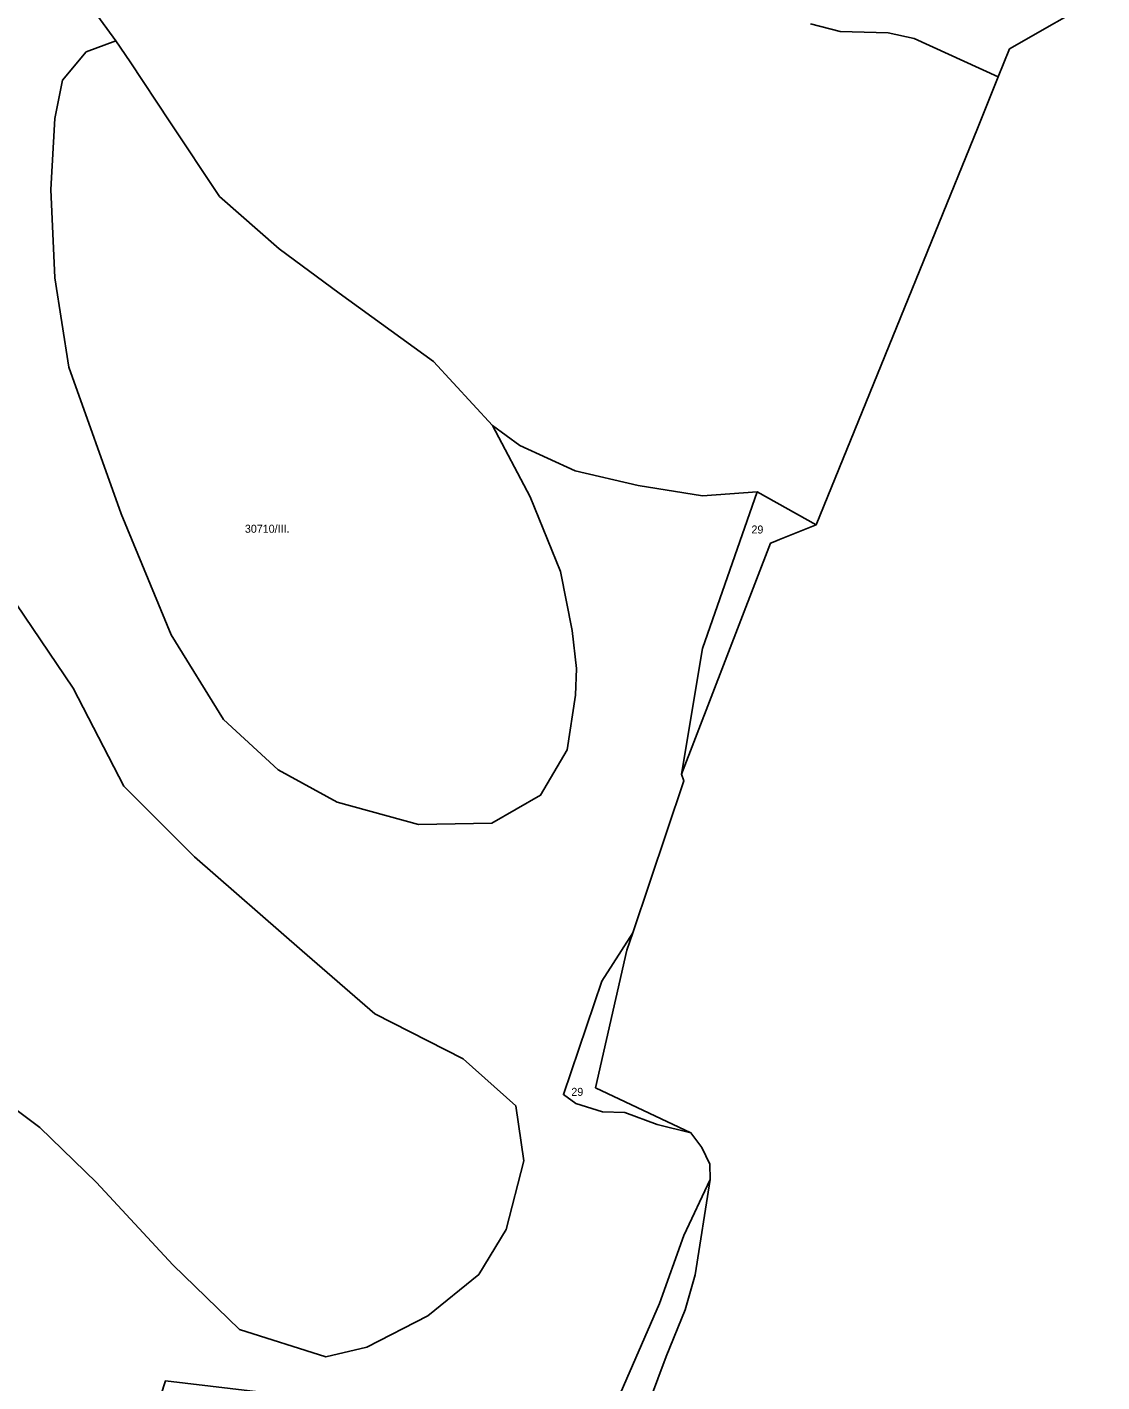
# Model space of a CAD drawing. Extents: x -521621 to -516761, y -1190184 to -1184927.
# Drawn here: x -518423 to -517886, y -1189440 to -1188763 of the extents above; entities that cross this region are included whole.
import ezdxf

# ---------------------------------------------------------------- set-up
doc = ezdxf.new("R2010")
doc.units = 0
doc.layers.add('BPEJ_s', color=7, linetype='Continuous')

msp = doc.modelspace()

# ---------------------------------------------------------------- linework, layer by layer
at = {"layer": 'BPEJ_s'}
for points in [[(-518480.44, -1188633.02), (-518467.36, -1188644.92), (-518453.88, -1188663.57), (-518442.78, -1188683.01), (-518435.53, -1188694.4), (-518417.8, -1188716.79), (-518378.87, -1188769.99)], [(-518031.53, -1188761.48), (-518016.61, -1188765.36), (-517992.7, -1188765.98), (-517979.61, -1188768.84), (-517937.55, -1188788.05), (-517947.94, -1188813.87), (-517990.27, -1188917.77), (-518028.72, -1189011.96), (-518058.18, -1188995.55), (-518085.57, -1188997.56), (-518117.61, -1188992.3), (-518149.12, -1188984.95), (-518176.95, -1188972.33), (-518190.61, -1188962.35), (-518220.02, -1188930.29), (-518267.29, -1188896.14), (-518297.22, -1188874.06), (-518327.16, -1188847.79), (-518351.84, -1188810.48), (-518371.8, -1188780.52), (-518378.87, -1188769.99), (-518417.8, -1188716.79)], [(-517885.74, -1188747.6), (-517931.92, -1188774.05), (-517937.55, -1188788.05), (-517979.61, -1188768.84), (-517992.7, -1188765.98), (-518016.61, -1188765.36), (-518031.53, -1188761.48)], [(-518378.87, -1188769.99), (-518393.69, -1188775.51), (-518405.6, -1188789.76), (-518409.38, -1188808.94), (-518411.41, -1188844.41), (-518409.38, -1188888.46), (-518402.4, -1188933.23), (-518376.26, -1189006.49), (-518351.27, -1189066.96), (-518325.12, -1189109.4), (-518297.81, -1189134.4), (-518268.17, -1189150.69), (-518227.5, -1189161.73), (-518190.89, -1189161.15), (-518166.49, -1189147.2), (-518153.12, -1189124.52), (-518149.05, -1189097.19), (-518148.47, -1189083.82), (-518150.69, -1189064.82), (-518156.47, -1189035.4), (-518171.7, -1188998.08), (-518190.61, -1188962.35)], [(-518190.61, -1188962.35), (-518176.95, -1188972.33), (-518149.12, -1188984.95), (-518117.61, -1188992.3), (-518085.57, -1188997.56), (-518058.18, -1188995.55)], [(-518058.18, -1188995.55), (-518085.58, -1189073.76), (-518095.96, -1189136.68)], [(-518428.75, -1189051.42), (-518400.33, -1189093.59), (-518374.85, -1189142.62), (-518339.57, -1189177.93), (-518285.66, -1189225), (-518249.4, -1189256.38), (-518205.29, -1189278.94), (-518178.83, -1189302.47), (-518174.91, -1189329.93), (-518183.73, -1189364.26), (-518197.45, -1189386.81), (-518222.94, -1189407.41), (-518253.32, -1189423.1), (-518273.9, -1189428), (-518317.02, -1189414.27), (-518350.35, -1189381.91), (-518388.57, -1189340.72), (-518416.99, -1189313.26), (-518464.04, -1189277.96)], [(-518464.04, -1189277.96), (-518416.99, -1189313.26), (-518388.57, -1189340.72), (-518350.35, -1189381.91), (-518317.02, -1189414.27), (-518273.9, -1189428), (-518253.32, -1189423.1), (-518222.94, -1189407.41), (-518197.45, -1189386.81), (-518183.73, -1189364.26), (-518174.91, -1189329.93), (-518178.83, -1189302.47), (-518205.29, -1189278.94), (-518249.4, -1189256.38), (-518285.66, -1189225), (-518339.57, -1189177.93), (-518374.85, -1189142.62), (-518400.33, -1189093.59), (-518428.75, -1189051.42)], [(-518095.96, -1189136.68), (-518094.83, -1189139.91), (-518120.38, -1189215.97)], [(-518120.38, -1189215.97), (-518135.91, -1189240.08), (-518155.06, -1189296.79), (-518148.9, -1189301.34), (-518135.48, -1189305.39), (-518124.34, -1189305.74), (-518108.21, -1189311.76), (-518091.28, -1189315.94), (-518085.78, -1189323.23)], [(-518085.78, -1189323.23), (-518081.89, -1189331.64), (-518081.72, -1189339.3)], [(-518081.72, -1189339.3), (-518094.78, -1189367.28), (-518107.05, -1189401.19), (-518136.87, -1189469.83), (-518141.3, -1189485.42), (-518148.62, -1189486.34), (-518144.38, -1189476), (-518214.9, -1189460.28), (-518266.87, -1189450.34), (-518354.11, -1189440.01), (-518356.45, -1189447.17), (-518274.52, -1189460.18), (-518175.78, -1189480.15), (-518177.97, -1189490.02), (-518179.21, -1189509.35)]]:
    msp.add_lwpolyline(points, dxfattribs=at)
for points in [[(-518378.87, -1188769.99), (-518371.8, -1188780.52), (-518351.84, -1188810.48), (-518327.16, -1188847.79), (-518297.22, -1188874.06), (-518267.29, -1188896.14), (-518220.02, -1188930.29), (-518190.61, -1188962.35), (-518171.7, -1188998.08), (-518156.47, -1189035.4), (-518150.69, -1189064.82), (-518148.47, -1189083.82), (-518149.05, -1189097.19), (-518153.12, -1189124.52), (-518166.49, -1189147.2), (-518190.89, -1189161.15), (-518227.5, -1189161.73), (-518268.17, -1189150.69), (-518297.81, -1189134.4), (-518325.12, -1189109.4), (-518351.27, -1189066.96), (-518376.26, -1189006.49), (-518402.4, -1188933.23), (-518409.38, -1188888.46), (-518411.41, -1188844.41), (-518409.38, -1188808.94), (-518405.6, -1188789.76), (-518393.69, -1188775.51)], [(-518095.96, -1189136.68), (-518085.58, -1189073.76), (-518058.18, -1188995.55), (-518028.72, -1189011.96), (-518037.89, -1189015.67), (-518047.06, -1189019.37), (-518049.3, -1189020.28), (-518051.53, -1189021.18)], [(-518120.38, -1189215.97), (-518135.91, -1189240.08), (-518155.06, -1189296.79), (-518148.9, -1189301.34), (-518135.48, -1189305.39), (-518124.34, -1189305.74), (-518108.21, -1189311.76), (-518091.28, -1189315.94), (-518138.99, -1189293.44), (-518123.28, -1189224.59)], [(-518179.21, -1189509.35), (-518177.97, -1189490.02), (-518175.78, -1189480.15), (-518274.52, -1189460.18), (-518356.45, -1189447.17), (-518354.11, -1189440.01), (-518266.87, -1189450.34), (-518214.9, -1189460.28), (-518144.38, -1189476), (-518148.62, -1189486.34), (-518141.3, -1189485.42), (-518136.87, -1189469.83), (-518107.05, -1189401.19), (-518094.78, -1189367.28), (-518081.72, -1189339.3), (-518089.17, -1189386.88), (-518094.18, -1189404.37), (-518103.69, -1189427.69), (-518125.04, -1189484.87), (-518110.32, -1189500.73), (-518121.9, -1189499.52), (-518133.91, -1189502.5), (-518164.27, -1189510.04)]]:
    msp.add_lwpolyline(points, close=True, dxfattribs=at)

# ---------------------------------------------------------------- texts
for s, p in [('30710/III.', (-518314.38, -1189015.95)), ('29', (-518061.02, -1189016.33)), ('29', (-518151.11, -1189297.46))]:
    msp.add_text(s, height=4, dxfattribs=at).set_placement(p)

doc.saveas('drawing.dxf')
